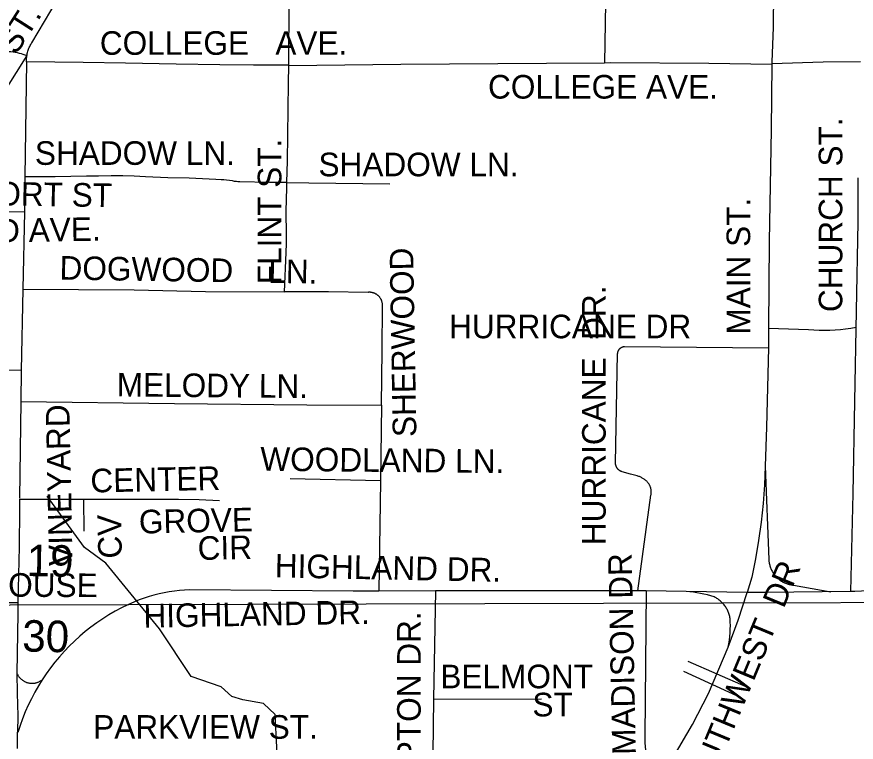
# Model space of a CAD drawing. Extents: x 1670563 to 1761545, y 515755 to 578944.
# Drawn here: x 1693708 to 1696373, y 543667 to 545971 of the extents above; entities that cross this region are included whole.
import ezdxf

# ---------------------------------------------------------------- set-up
doc = ezdxf.new("R2010")
doc.units = 0
for name, color, linetype in [('5_sectionlines', 7, 'Continuous'), ('62_text', 7, 'Continuous'), ('SHP_LINE', 7, 'Continuous'), ('STREETCL', 7, 'Continuous'), ('STRNAMES', 7, 'Continuous')]:
    doc.layers.add(name, color=color, linetype=linetype)

msp = doc.modelspace()

# ---------------------------------------------------------------- linework, layer by layer
at = {"layer": '5_sectionlines'}
msp.add_lwpolyline([(1685823.9, 543970.2), (1688486.3, 544044.1), (1693687.1, 544103.2), (1698961.5, 544118.1), (1704285.9, 544155), (1709574.3, 544171.9), (1714958.5, 544246.7), (1716656.1, 544265.6)], dxfattribs=at)
at = {"layer": 'DEFPOINTS'}
for p, q in [((1695839.1, 543924), (1696022.4, 543843.9)), ((1695824.9, 543892.3), (1696006.6, 543808.7))]:
    msp.add_line(p, q, dxfattribs=at)
at = {"layer": 'SHP_LINE'}
msp.add_lwpolyline([(1694571, 543125), (1694563, 543186), (1694545, 543273), (1694536, 543356), (1694533, 543462), (1694530, 543548), (1694535, 543622), (1694534, 543651), (1694528, 543755), (1694491, 543790), (1694426, 543801), (1694391, 543812), (1694357, 543843), (1694261, 543876), (1694161, 544027), (1693990, 544236), (1693923, 544285), (1693804, 544448)], dxfattribs=at)
at = {"layer": 'STREETCL'}
for points in [[(1695589, 546762.6), (1695585.4, 546611.4), (1695584.2, 546452), (1695581.2, 546252), (1695577.5, 546014.3), (1695574.3, 545825.4)], [(1696122.6, 546750.8), (1696119.3, 546632.9), (1696119.5, 546588.9), (1696118.3, 546545.1), (1696115.8, 546501.2), (1696112.3, 546146.1), (1696111.1, 546050.1), (1696109.8, 545938.3), (1696105.9, 545826.6), (1696105.8, 545821.2)], [(1694571.3, 545817.4), (1694571.5, 545848.3), (1694574.7, 546285.5)], [(1693739.7, 545848.3), (1693740.3, 545851.6), (1693741, 545854.9), (1693741.8, 545858.2), (1693742.7, 545861.5), (1693743.8, 545864.7), (1693744.9, 545867.9), (1693746.1, 545871), (1693747.4, 545874.1), (1693748.9, 545877.2), (1693750.4, 545880.2), (1693752, 545883.2), (1693753.8, 545886.1), (1693755.6, 545888.9), (1693835.9, 546025.2)], [(1693385, 545858.8), (1693590.7, 545861.6), (1693669.7, 545861.6), (1693676.2, 545861.5), (1693682.7, 545861.1), (1693689.2, 545860.6), (1693695.7, 545859.8), (1693702.1, 545858.8), (1693708.5, 545857.6), (1693714.9, 545856.1), (1693721.2, 545854.5), (1693727.4, 545852.6), (1693733.6, 545850.6), (1693739.7, 545848.3)], [(1693739.7, 545848.3), (1693603.2, 545632.3), (1693452.9, 545404.3), (1693426.1, 545364.1), (1693415, 545345.8)], [(1693738.3, 545828.5), (1693738.3, 545832.5), (1693738.5, 545836.5), (1693738.8, 545840.4), (1693739.2, 545844.4), (1693739.7, 545848.3)], [(1693738.3, 545828.5), (1693733.4, 545463.1)], [(1694571.3, 545817.4), (1694459, 545817.4), (1694352.3, 545818.3), (1694213.8, 545821.1), (1694053, 545823.5), (1693918.1, 545826.2), (1693738.3, 545828.5)], [(1694565.3, 545446.1), (1694567, 545512.8), (1694570.8, 545760), (1694571.3, 545816.4)], [(1694571.3, 545816.4), (1694927.4, 545821.1), (1695389.4, 545823.4), (1695574.3, 545825.4)], [(1694571.3, 545816.4), (1694571.3, 545817.4)], [(1695574.3, 545825.4), (1695592.7, 545825.6), (1695905.9, 545824.1), (1696105.8, 545820.4)], [(1696105.8, 545820.4), (1696103.5, 545611.7), (1696096.5, 545258.5), (1696095.4, 544982.2)], [(1696387, 545827.7), (1696268.1, 545826.6), (1696105.8, 545821.2)], [(1693733.4, 545463.1), (1693732.7, 545391.3), (1693731.9, 545351.3)], [(1693733.4, 545463.5), (1693829.7, 545464.1), (1693929, 545466.3), (1693967.7, 545466.2), (1694007.8, 545466.7), (1694044.1, 545466.5), (1694080.2, 545465.4), (1694116.4, 545463.3), (1694187.6, 545460.7), (1694255.2, 545459.5), (1694340.3, 545454.8), (1694356.4, 545454.4), (1694365.2, 545453.9), (1694373.9, 545453.2), (1694382.7, 545452.2), (1694391.4, 545451), (1694394.9, 545450.2), (1694398.5, 545449.5), (1694402, 545449), (1694405.6, 545448.6), (1694409.2, 545448.3), (1694412.8, 545448.1), (1694416.4, 545448), (1694510.5, 545446.3), (1694565.3, 545446.1)], [(1694557.8, 545097.2), (1694563.4, 545222), (1694564.2, 545250.5), (1694564.1, 545279), (1694563.5, 545353.6), (1694564.8, 545428.2), (1694565.2, 545443.6)], [(1694565.2, 545443.6), (1694565.3, 545446.1)], [(1694892.6, 545439.2), (1694635.2, 545442.5), (1694565.2, 545443.6)], [(1696356.8, 544145.2), (1696364, 544456.3), (1696368.6, 544748.8), (1696373.9, 545037.4), (1696379.3, 545318.4), (1696379.7, 545459.1)], [(1693731.9, 545351.3), (1693415, 545345.8)], [(1693731.9, 545351.3), (1693726.9, 545105.9)], [(1693726.9, 545105.9), (1693721.6, 544848)], [(1693726.9, 545105.9), (1694080.2, 545104.3), (1694307.2, 545098.4), (1694557.8, 545097.2)], [(1694865.4, 544737.6), (1694868.3, 544911.9), (1694868.9, 545052), (1694869, 545053.4), (1694869, 545054.8), (1694869, 545056.3), (1694868.9, 545057.7), (1694868.8, 545059.1), (1694868.6, 545060.6), (1694868.4, 545062), (1694868.1, 545063.4), (1694867.7, 545064.8), (1694867.4, 545066.2), (1694866.9, 545067.5), (1694866.5, 545068.9), (1694866, 545070.2), (1694865.4, 545071.5), (1694864.8, 545072.8), (1694864.1, 545074.1), (1694863.4, 545075.4), (1694862.7, 545076.6), (1694861.9, 545077.8), (1694861.1, 545079), (1694860.2, 545080.1), (1694859.3, 545081.2), (1694858.4, 545082.3), (1694857.4, 545083.3), (1694856.4, 545084.4), (1694855.3, 545085.3), (1694854.3, 545086.3), (1694853.2, 545087.2), (1694852, 545088), (1694850.8, 545088.9), (1694849.6, 545089.6), (1694848.4, 545090.4), (1694847.2, 545091.1), (1694845.9, 545091.7), (1694844.6, 545092.4), (1694843.3, 545092.9), (1694841.9, 545093.4), (1694840.6, 545093.9), (1694839.2, 545094.3), (1694837.8, 545094.7), (1694836.4, 545095), (1694835, 545095.3), (1694833.6, 545095.5), (1694832.2, 545095.7), (1694830.8, 545095.9), (1694829.3, 545095.9), (1694827.9, 545096), (1694826.5, 545096), (1694825, 545095.9), (1694823.6, 545095.8), (1694697.5, 545097.2), (1694557.8, 545097.2)], [(1696095.4, 544982.2), (1696222.3, 544977.3), (1696239, 544976.9), (1696255.8, 544976), (1696272.6, 544975.6), (1696289.4, 544975.8), (1696306.3, 544976.5), (1696323, 544977.9), (1696339.8, 544979.7), (1696356.4, 544982.2), (1696373, 544985.2)], [(1696095.4, 544982.2), (1696095.3, 544953.3), (1696094.5, 544919.6)], [(1695679.5, 544147.4), (1695721.5, 544451.9), (1695721.8, 544453.5), (1695722.1, 544455.1), (1695722.3, 544456.7), (1695722.4, 544458.3), (1695722.5, 544459.9), (1695722.6, 544461.5), (1695722.5, 544463.1), (1695722.5, 544464.7), (1695722.3, 544466.3), (1695722.2, 544467.9), (1695721.9, 544469.5), (1695721.6, 544471.1), (1695721.3, 544472.7), (1695720.9, 544474.3), (1695720.4, 544475.8), (1695719.9, 544477.4), (1695719.3, 544478.9), (1695718.7, 544480.4), (1695718, 544481.8), (1695717.3, 544483.3), (1695716.5, 544484.7), (1695715.7, 544486.1), (1695714.8, 544487.5), (1695713.9, 544488.8), (1695713, 544490.1), (1695712, 544491.3), (1695710.9, 544492.6), (1695709.8, 544493.8), (1695708, 544495.5), (1695706.2, 544497.2), (1695704.3, 544498.8), (1695702.3, 544500.4), (1695700.3, 544501.9), (1695698.2, 544503.3), (1695696.1, 544504.7), (1695693.9, 544506), (1695691.7, 544507.2), (1695689.5, 544508.3), (1695687.2, 544509.3), (1695684.9, 544510.3), (1695682.6, 544511.2), (1695680.2, 544512), (1695677.8, 544512.8), (1695656.9, 544518.5), (1695629.8, 544526.1), (1695628.8, 544526.4), (1695627.9, 544526.7), (1695627, 544527.1), (1695626.1, 544527.4), (1695625.2, 544527.9), (1695624.3, 544528.3), (1695623.4, 544528.8), (1695622.6, 544529.3), (1695621.8, 544529.8), (1695621, 544530.4), (1695620.2, 544531), (1695619.4, 544531.6), (1695618.7, 544532.3), (1695617.9, 544532.9), (1695617.2, 544533.6), (1695616.6, 544534.4), (1695615.9, 544535.1), (1695615.3, 544535.9), (1695614.7, 544536.7), (1695614.1, 544537.5), (1695613.6, 544538.3), (1695613.1, 544539.1), (1695612.6, 544540), (1695612.2, 544540.9), (1695611.7, 544541.8), (1695611.3, 544542.7), (1695611, 544543.6), (1695610.7, 544544.5), (1695610.4, 544545.5), (1695610.1, 544546.4), (1695609.9, 544547.4), (1695609.7, 544548.3), (1695609.5, 544549.3), (1695609.4, 544550.3), (1695609.3, 544551.3), (1695609.2, 544552.3), (1695609.2, 544553.2), (1695615.8, 544901.1), (1695615.9, 544902), (1695615.9, 544902.8), (1695616, 544903.6), (1695616.2, 544904.5), (1695616.4, 544905.3), (1695616.6, 544906.1), (1695616.8, 544906.9), (1695617, 544907.7), (1695617.3, 544908.5), (1695617.6, 544909.3), (1695617.9, 544910), (1695618.3, 544910.8), (1695618.7, 544911.5), (1695619.1, 544912.2), (1695619.5, 544913), (1695620, 544913.6), (1695620.5, 544914.3), (1695621, 544915), (1695621.5, 544915.6), (1695622.1, 544916.3), (1695622.7, 544916.9), (1695623.3, 544917.5), (1695623.9, 544918), (1695624.5, 544918.6), (1695625.2, 544919.1), (1695625.8, 544919.6), (1695626.5, 544920.1), (1695627.2, 544920.5), (1695627.9, 544920.9), (1695628.7, 544921.3), (1695629.4, 544921.7), (1695630.2, 544922.1), (1695631, 544922.4), (1695631.7, 544922.7), (1695632.5, 544922.9), (1695633.3, 544923.2), (1695634.1, 544923.4), (1695635, 544923.6), (1695635.8, 544923.7), (1695636.6, 544923.9), (1695637.4, 544924), (1696094.5, 544919.6)], [(1696094.5, 544919.6), (1696088.3, 544667.5), (1696084.7, 544543.5), (1696082.1, 544484.3), (1696077.7, 544425.2), (1696071.5, 544366.2), (1696063.5, 544307.5), (1696053.7, 544249.1), (1696042.1, 544190.9), (1696027.3, 544142.6)], [(1693122.5, 544880.2), (1693171.1, 544857.1), (1693721.6, 544848.2)], [(1693721.6, 544848), (1693720.4, 544749.5)], [(1693720.4, 544749.5), (1693716.7, 544441.7)], [(1693720.4, 544749.5), (1694208.5, 544743.1), (1694628.8, 544738.7), (1694865.4, 544737.6)], [(1694865.4, 544737.6), (1694863.1, 544497.4)], [(1696084.7, 544543.5), (1696095.9, 544247.1), (1696096.1, 544244.1), (1696096.4, 544241.2), (1696096.8, 544238.3), (1696097.3, 544235.4), (1696097.9, 544232.5), (1696098.6, 544229.6), (1696099.3, 544226.8), (1696100.2, 544224), (1696101.2, 544221.2), (1696102.3, 544218.5), (1696103.4, 544215.8), (1696104.7, 544213.1), (1696106, 544210.5), (1696107.5, 544207.9), (1696109, 544205.4), (1696110.6, 544203), (1696112.3, 544200.5), (1696114.1, 544198.2), (1696115.9, 544195.9), (1696117.9, 544193.7), (1696119.9, 544191.5), (1696122, 544189.5), (1696124.1, 544187.5), (1696126.3, 544185.5), (1696128.6, 544183.7), (1696131, 544181.9), (1696133.4, 544180.2), (1696135.8, 544178.6), (1696138.3, 544177), (1696140.9, 544175.6), (1696143.5, 544174.3), (1696146.2, 544173), (1696148.9, 544171.8), (1696151.6, 544170.8), (1696154.4, 544169.8), (1696157.2, 544168.9), (1696160, 544168.1), (1696162.9, 544167.4), (1696165.8, 544166.8), (1696168.7, 544166.3), (1696171.6, 544165.9), (1696174.5, 544165.6), (1696292.5, 544144.4)], [(1694863.1, 544497.4), (1694576.1, 544503)], [(1694863.1, 544497.4), (1694857.5, 544146.8)], [(1693716.7, 544439), (1693716.7, 544406.1), (1693714.8, 544287.6), (1693711.4, 544109.3)], [(1693716.7, 544439), (1693920.8, 544439)], [(1693921.6, 544337.5), (1693920.8, 544439)], [(1693920.8, 544439), (1693998.5, 544439), (1694221.5, 544438.5), (1694286.5, 544437.3), (1694351.5, 544434.2)], [(1696920.6, 544157.9), (1696795.2, 544158.4), (1696582.1, 544155.6), (1696369.2, 544145.4), (1696356.8, 544145.2)], [(1694857.5, 544146.8), (1694776.4, 544146.6), (1694257.2, 544150.7), (1694240.7, 544150), (1694224.3, 544148.7), (1694208, 544146.9), (1694191.7, 544144.5), (1694175.5, 544141.6), (1694159.4, 544138.2), (1694143.4, 544134.2), (1694127.6, 544129.7), (1694111.9, 544124.7), (1694096.4, 544119.1), (1694081.1, 544113.1), (1694060.3, 544103.6), (1694039.8, 544093.4), (1694019.7, 544082.6), (1693999.9, 544071), (1693980.6, 544058.7), (1693961.7, 544045.8), (1693943.3, 544032.3), (1693925.3, 544018.1), (1693907.9, 544003.3), (1693890.9, 543987.9), (1693874.5, 543972), (1693858.7, 543955.5), (1693843.4, 543938.4), (1693828.8, 543920.8), (1693814.7, 543902.8), (1693801.3, 543884.2), (1693788.6, 543865.2)], [(1695037.5, 544147.1), (1694857.5, 544146.8)], [(1695037.5, 544147.1), (1695031.5, 543803.4)], [(1695679.5, 544147.4), (1695458.7, 544148), (1695037.5, 544147.1)], [(1695706.8, 544147.3), (1695679.5, 544147.4)], [(1695706.8, 544147.3), (1695702, 543684.6)], [(1695833.5, 544145.5), (1695706.8, 544147.3)], [(1696027.3, 544142.6), (1695833.5, 544145.5)], [(1695966.7, 543968.2), (1695968.8, 543979.5), (1695970.6, 543990.9), (1695972, 544002.4), (1695973, 544014), (1695973.5, 544025.5), (1695973.7, 544037.1), (1695973.4, 544048.6), (1695972.8, 544060.2), (1695972.3, 544063.3), (1695971.6, 544066.3), (1695970.9, 544069.4), (1695970, 544072.4), (1695969.1, 544075.4), (1695968, 544078.3), (1695966.9, 544081.2), (1695965.6, 544084.1), (1695964.3, 544086.9), (1695962.8, 544089.7), (1695961.3, 544092.4), (1695959.7, 544095.1), (1695958, 544097.7), (1695956.1, 544100.3), (1695954.2, 544102.8), (1695952.3, 544105.2), (1695950.2, 544107.6), (1695948.1, 544109.8), (1695945.8, 544112.1), (1695943.5, 544114.2), (1695941.2, 544116.2), (1695938.7, 544118.2), (1695936.2, 544120.1), (1695933.7, 544121.9), (1695931, 544123.6), (1695928.4, 544125.2), (1695925.6, 544126.7), (1695922.8, 544128.2), (1695912, 544131.6), (1695901, 544134.6), (1695889.9, 544137.3), (1695878.7, 544139.6), (1695867.5, 544141.5), (1695856.2, 544143.1), (1695844.8, 544144.3), (1695833.5, 544145.2)], [(1695966.7, 543968.2), (1695998.3, 544054.9), (1696027.3, 544142.6)], [(1696356.8, 544145.2), (1696084.6, 544141.8), (1696027.3, 544142.6)], [(1693711.4, 544109.3), (1693569.1, 544109.3), (1693562.2, 544109.1), (1693555.3, 544108.8), (1693548.4, 544108.2), (1693541.5, 544107.3), (1693534.7, 544106.2), (1693527.9, 544104.9), (1693521.1, 544103.4), (1693514.4, 544101.6), (1693507.8, 544099.5), (1693501.3, 544097.3), (1693494.8, 544094.8), (1693488.4, 544092.1), (1693482.2, 544089.1), (1693476, 544086), (1693470, 544082.6)], [(1693711.4, 544109.3), (1693710.8, 544075.8), (1693708.1, 543885.7)], [(1695751.2, 543559.5), (1695791.9, 543618.6), (1695853.7, 543722.5), (1695904.1, 543822), (1695966.7, 543968.2)], [(1693708.1, 543885.9), (1693709.3, 543822.9), (1693710.5, 543750.6), (1693710.3, 543698.6)], [(1693708.1, 543885.7), (1693708.9, 543884), (1693709.7, 543882.4), (1693710.5, 543880.8), (1693711.4, 543879.2), (1693712.4, 543877.7), (1693713.4, 543876.2), (1693714.4, 543874.7), (1693715.5, 543873.3), (1693716.7, 543871.9), (1693717.9, 543870.5), (1693719.2, 543869.2), (1693720.5, 543868), (1693721.8, 543866.8), (1693723.2, 543865.6), (1693724.6, 543864.5), (1693726.1, 543863.4), (1693727.6, 543862.4), (1693729.1, 543861.4), (1693730.7, 543860.5), (1693732.2, 543859.6), (1693733.9, 543858.8), (1693735.5, 543858.1), (1693737.2, 543857.4), (1693738.9, 543856.8), (1693740.6, 543856.2), (1693742.4, 543855.7), (1693744.1, 543855.3), (1693745.9, 543854.9), (1693747.7, 543854.6), (1693749.5, 543854.3), (1693751.3, 543854.1), (1693753.1, 543854), (1693754.9, 543853.9), (1693756.7, 543853.9), (1693758.5, 543853.9), (1693760.3, 543854.1), (1693762.1, 543854.2), (1693763.9, 543854.5), (1693765.7, 543854.8), (1693767.5, 543855.2), (1693769.2, 543855.6), (1693771, 543856.1), (1693772.7, 543856.6), (1693774.4, 543857.3), (1693776.1, 543857.9), (1693777.7, 543858.7), (1693779.4, 543859.4), (1693781, 543860.3), (1693782.5, 543861.2), (1693784.1, 543862.1), (1693785.6, 543863.1), (1693787.1, 543864.2), (1693788.5, 543865.3)], [(1693788.6, 543865.2), (1693776.3, 543845.6), (1693764.8, 543825.4), (1693753.9, 543804.9), (1693743.8, 543784.1), (1693734.4, 543762.9), (1693725.7, 543741.4), (1693717.9, 543719.5), (1693710.7, 543697.5)], [(1695031.5, 543803.4), (1695028.6, 543630.4)], [(1695031.5, 543803.4), (1695373.5, 543804.3)], [(1693710.1, 543646.5), (1693710.3, 543698.6)]]:
    msp.add_lwpolyline(points, dxfattribs=at)
msp.add_arc((1695935.2, 543678.5), 233.4, 178.4957, 189.7067, dxfattribs=at)

# ---------------------------------------------------------------- texts
at = {"layer": '62_text'}
for s, rotation, p in [('19', 358.9302, (1693738.2, 544194.6)), ('30', 358.9311, (1693724.4, 543954.9))]:
    msp.add_text(s, height=100, rotation=rotation, dxfattribs=at).set_placement(p)
at = {"layer": 'STRNAMES'}
for s, rotation, p in [('WOOD ST.', 57.3764, (1693516.4, 545552)), ('CHURCH ST.', 90, (1696329.4, 545033.1)), ('FLINT ST.', 90, (1694547.9, 545121.5)), ('SHORT ST', 359.1009, (1693502.8, 545374.4)), ('MAIN ST.', 90, (1696036.7, 544961.6)), ('ROSEMOND AVE.', 1, (1693127.6, 545245.1)), ('SHERWOOD', 91, (1694976.9, 544636.8)), ('DOGWOOD    LN.', 359.1085, (1693843, 545136.3)), ('HURRICANE  DR.', 90, (1695577.9, 544292.8)), ('MELODY LN.', 359.494, (1694024.7, 544765.2)), ('VINEYARD', 91.2, (1693885.2, 544228)), ('WOODLAND LN.', 359.438, (1694480.9, 544529.1)), ('CENTER ', 1.2, (1693942.2, 544459.9)), ('GROVE ', 1.2, (1694096.2, 544329.4)), ('CV', 91.2, (1694041.6, 544250.9)), ('CIR', 1.2, (1694282.7, 544245.4)), ('HIGHLAND DR.', 358.8816, (1694526.5, 544190.3)), ('MADISON DR', 91.196, (1695673.8, 543627.3)), ('SOUTHWEST  DR', 67.4965, (1695876.7, 543445.7)), ('CULBERHOUSE ', 359.6971, (1693200.9, 544131.5)), ('HIGHLAND DR.', 1, (1694110.5, 544030.4)), ('HAMPTON DR.', 90, (1694990.5, 543380.4))]:
    msp.add_text(s, height=75, rotation=rotation, dxfattribs=at).set_placement(p)
for s, p in [('COLLEGE   AVE.', (1693971.4, 545850.3)), ('COLLEGE AVE.', (1695204.2, 545711.3)), ('SHADOW LN.', (1693765.2, 545500.8)), ('SHADOW LN.', (1694665.8, 545464.5)), ('HURRICANE DR', (1695080.5, 544949.9)), ('BELMONT', (1695052.8, 543838.1)), (' ST', (1695317.3, 543748.8)), ('PARKVIEW ST.', (1693950.4, 543677.7))]:
    msp.add_text(s, height=75, dxfattribs=at).set_placement(p)

doc.saveas('drawing.dxf')
